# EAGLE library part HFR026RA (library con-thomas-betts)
THOMAS&BETTS
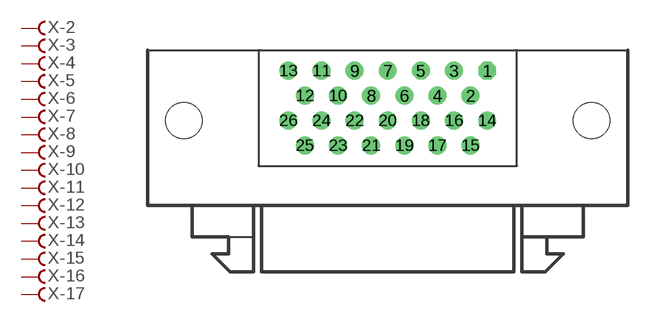
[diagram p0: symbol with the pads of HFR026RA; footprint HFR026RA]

Designator prefix X; gates -2=F -3=F -4=F -5=F -6=F -7=F -8=F -9=F -10=F -11=F -12=F -13=F -14=F -15=F -16=F -17=F -18=F -19=F -20=F -21=F -22=F -23=F -24=F -25=F -26=F -1=FV

## HFR026RA (OC_FARNELL: unknown; OC_NEWARK: unknown)  [HFR026RA]
1  -1:F  pas
2  -2:F  pas
3  -3:F  pas
4  -4:F  pas
5  -5:F  pas
6  -6:F  pas
7  -7:F  pas
8  -8:F  pas
9  -9:F  pas
10  -10:F  pas
11  -11:F  pas
12  -12:F  pas
13  -13:F  pas
14  -14:F  pas
15  -15:F  pas
16  -16:F  pas
17  -17:F  pas
18  -18:F  pas
19  -19:F  pas
20  -20:F  pas
21  -21:F  pas
22  -22:F  pas
23  -23:F  pas
24  -24:F  pas
25  -25:F  pas
26  -26:F  pas

## Footprint HFR026RA (pad centres in mm)
THOMAS&BETTS Fine Pitch "D" Connector HFR026RA29xxx
drill 0.864 octagon: 1 7.62,8.89
drill 0.864 round: 2 6.35,6.98; 3 5.08,8.89; 4 3.81,6.98; 5 2.54,8.89; 6 1.27,6.98; 7 0,8.89; 8 -1.27,6.98; 9 -2.54,8.89; 10 -3.81,6.98; 11 -5.08,8.89; 12 -6.35,6.98; 13 -7.62,8.89; 14 7.62,5.07; 15 6.35,3.16; 16 5.08,5.07; 17 3.81,3.16; 18 2.54,5.07; 19 1.27,3.16; 20 0,5.07; 21 -1.27,3.16; 22 -2.54,5.07; 23 -3.81,3.16; 24 -5.08,5.07; 25 -6.35,3.16; 26 -7.62,5.07
hole 2.769 at 15.621,5.07
hole 2.769 at -15.621,5.07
